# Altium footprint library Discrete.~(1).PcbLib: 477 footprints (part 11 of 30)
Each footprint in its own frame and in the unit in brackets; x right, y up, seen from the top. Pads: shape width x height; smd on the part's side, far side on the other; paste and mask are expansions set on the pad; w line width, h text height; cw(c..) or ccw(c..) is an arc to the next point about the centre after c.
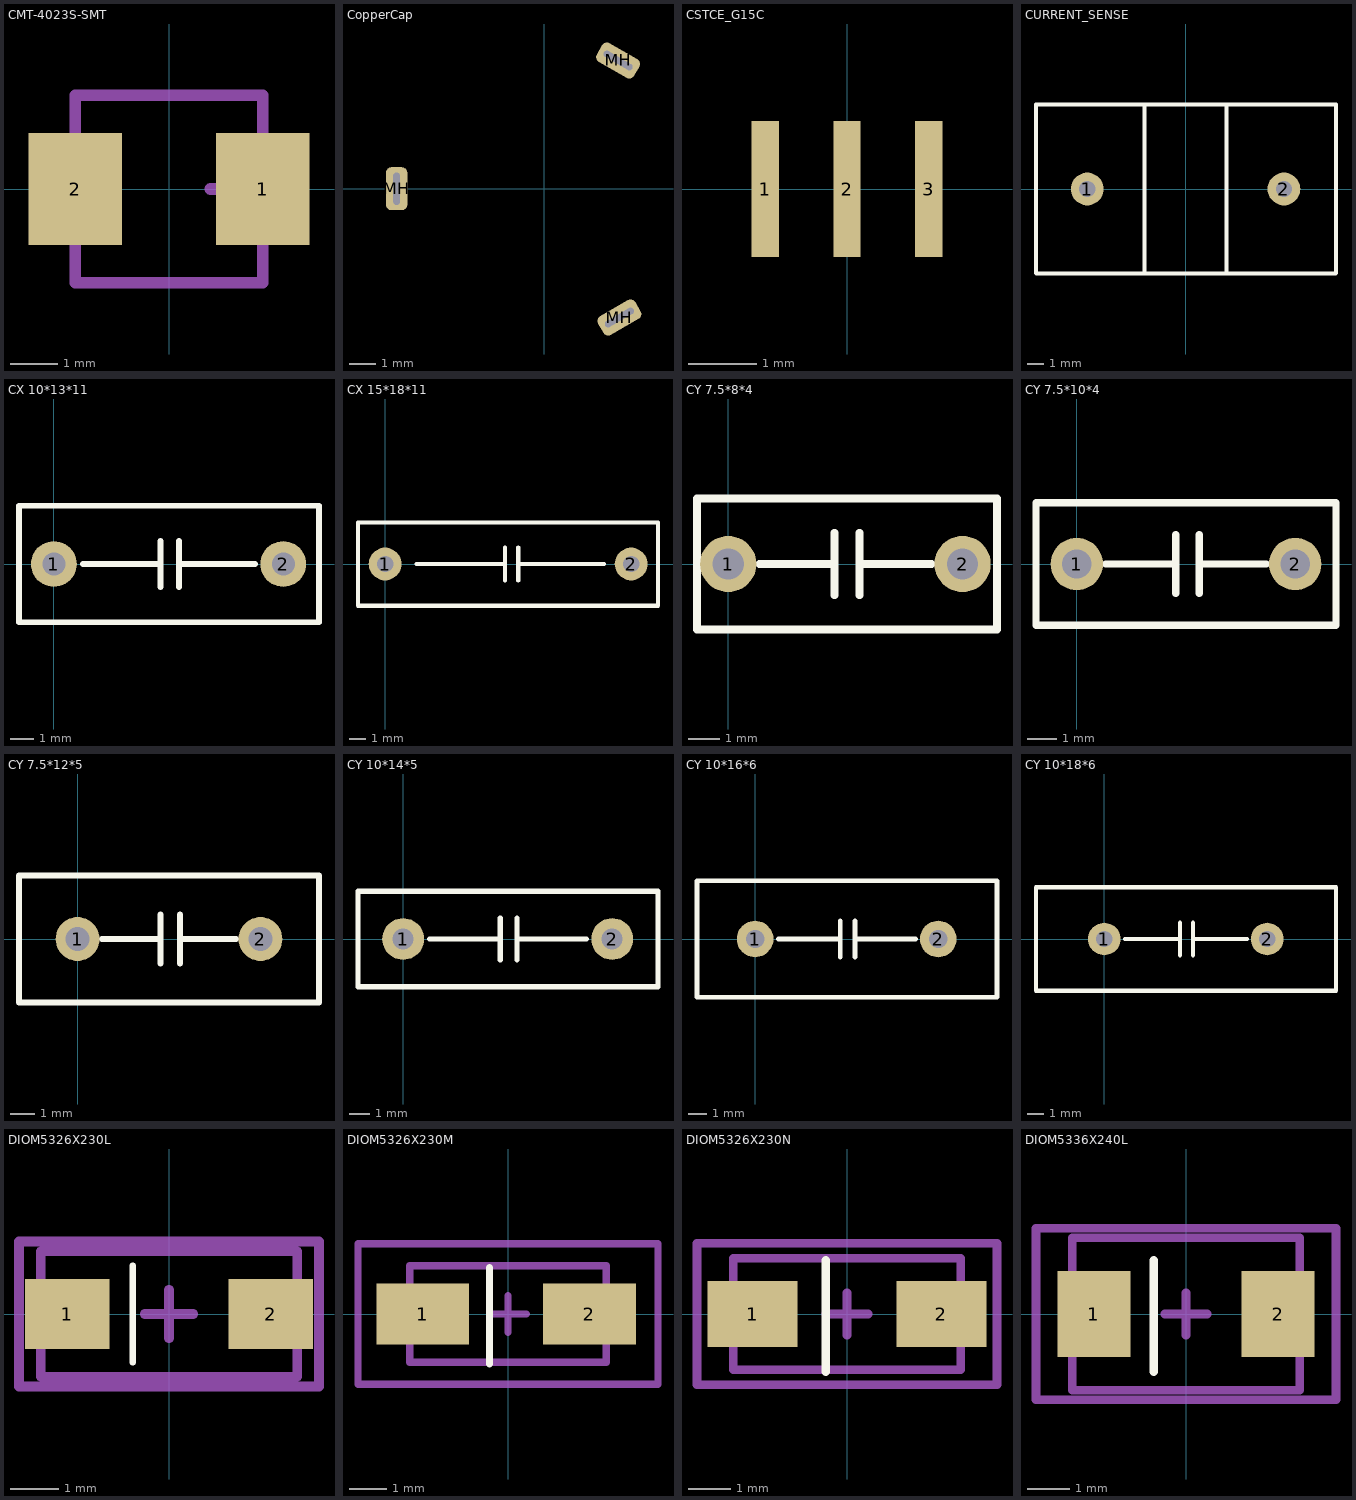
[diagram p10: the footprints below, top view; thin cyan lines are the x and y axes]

## CMT-4023S-SMT [mm]
pads (2):
  rect 2x2.4 smd: 1(2,0) 2(-2,0)
Mechanical 13:
  lines w0.254: 0.889,0 1.651,0 ; 1.27,-0.381 1.27,0.381 ; -2,-2 -2,2 2,2 2,-2 -2,-2
3D body "CUI_INC_CMT-4023S-SMT.step": height 2, standoff 0, extent -2,-2 2,2

## CopperCap [mm]
pads (3):
  rrect50% 0.8x1.6 hole 0.24 slot 1.2 at 90 deg: MH(-5.5,0)
  rrect50% 0.8x1.6 hole 0.24 slot 1.2 at 150 deg rot 60: MH(2.751,4.776)
  rrect50% 0.8x1.6 hole 0.24 slot 1.2 at 30 deg rot 120: MH(2.8,-4.8)
3D body "copper cap v5.step": height 2.1, standoff -0.9, extent -8.879,-8.879 8.869,8.863

## CSTCE_G15C [mm]
pads (3):
  rect 0.4x2 smd: 1(-1.2,0) 2(0,0) 3(1.2,0)
3D body "SW3dPS-CSTCE.STEP": height 0.7, standoff 0, extent -1.6,-0.65 1.6,0.65

## CURRENT_SENSE [mm]
pads (2):
  round 2 hole 1: 1(-6,0) 2(6,0)
Top Overlay:
  lines w0.254: -2.5,-5.125 -2.5,5.15 ; 2.5,-5.15 2.5,5.075 ; 9.15,-5.15 -9.1,-5.15 -9.125,-5.125 -9.125,5.15 9.175,5.15 9.175,-5.125

## CX 10*13*11 [mm] "脚距10mm高13mm厚11mm"
pads (2):
  round 2 hole 1: 1(0,0) 2(10,0)
Top Overlay:
  lines w0.254: 1.27,0 4.55,0 ; 4.65,-1 4.65,1 ; 5.45,-1 5.45,1 ; 5.45,0 8.763,0 ; -1.524,-2.54 -1.524,2.54 11.557,2.54 11.557,-2.54 -1.524,-2.54
3D body "CX 10X13X11.STEP": height 11.02, standoff -3.48, extent -1.5,-2.5 11.5,2.5

## CX 15*18*11 [mm] "脚距15mm高18mm厚11mm"
pads (2):
  round 2 hole 1: 1(0,0) 2(15,0)
Top Overlay:
  lines w0.254: 1.905,0 7.217,0 ; 7.317,-1 7.317,1 ; 8.117,-1 8.117,1 ; 8.117,0 13.335,0 ; -1.651,-2.54 -1.651,2.54 16.637,2.54 16.637,-2.54 -1.651,-2.54
3D body "CX 15X18X11.STEP": height 11.02, standoff -3.48, extent -1.5,-2.5 16.5,2.5

## CY 7.5*8*4 [mm] "脚距7.5mm，直径8mm，厚4mm"
pads (2):
  round 1.8 hole 1: 1(0,0) 2(7.5,0)
Top Overlay:
  lines w0.254: 1,0 3.3,0 ; 3.4,-1 3.4,1 ; 4.2,-1 4.2,1 ; 4.2,0 6.5,0 ; -1,-2.1 -1,2.1 8.6,2.1 8.6,-2.1 -1,-2.1
3D body "CY 7.5X8X4.STEP": height 8.2, standoff -3.3, extent -0.292,-2 7.792,2

## CY 7.5*10*4 [mm] "脚距7.5mm，直径10mm，厚4mm"
pads (2):
  round 1.8 hole 1: 1(0,0) 2(7.5,0)
Top Overlay:
  lines w0.254: 1,0 3.3,0 ; 3.4,-1 3.4,1 ; 4.2,-1 4.2,1 ; 4.2,0 6.5,0 ; -1.4,-2.1 -1.4,2.1 8.9,2.1 8.9,-2.1 -1.4,-2.1
3D body "CY 7.5X10X4.STEP": height 10.2, standoff -3.3, extent -1.13,-2 8.87,2

## CY 7.5*12*5 [mm] "脚距7.5mm，直径12mm，厚5mm"
pads (2):
  round 1.8 hole 1: 1(0,0) 2(7.5,0)
Top Overlay:
  lines w0.254: 1,0 3.3,0 ; 3.4,-1 3.4,1 ; 4.2,-1 4.2,1 ; 4.2,0 6.5,0 ; -2.4,-2.6 -2.4,2.6 9.9,2.6 9.9,-2.6 -2.4,-2.6
3D body "CY 7.5X12X5.STEP": height 12.2, standoff -3.3, extent -2.25,-2.5 9.75,2.5

## CY 10*14*5 [mm] "脚距10mm，直径14mm，厚5mm"
pads (2):
  round 2 hole 1: 1(0,0) 2(10,0)
Top Overlay:
  lines w0.254: 1.27,0 4.55,0 ; 4.65,-1 4.65,1 ; 5.45,-1 5.45,1 ; 5.45,0 8.763,0 ; -2.159,-2.286 -2.159,2.286 12.192,2.286 12.192,-2.286 -2.159,-2.286
3D body "CY 10X14X5.STEP": height 14.2, standoff -3.3, extent -2,-2 12,2

## CY 10*16*6 [mm] "脚距10mm，直径16mm，厚6mm"
pads (2):
  round 2 hole 1: 1(0,0) 2(10,0)
Top Overlay:
  lines w0.254: 1.27,0 4.55,0 ; 4.65,-1 4.65,1 ; 5.45,-1 5.45,1 ; 5.45,0 8.763,0 ; -3.175,-3.175 13.208,-3.175 13.208,3.175 -3.175,3.175 -3.175,-3.175
3D body "CY 10X16X6.STEP": height 16.2, standoff -3.3, extent -3,-3 13,3

## CY 10*18*6 [mm] "脚距10mm，直径18mm，厚6mm"
pads (2):
  round 2 hole 1: 1(0,0) 2(10,0)
Top Overlay:
  lines w0.254: 1.27,0 4.55,0 ; 4.65,-1 4.65,1 ; 5.45,-1 5.45,1 ; 5.45,0 8.763,0 ; -4.191,-3.175 -4.191,3.175 14.224,3.175 14.224,-3.175 -4.191,-3.175
3D body "CY 10X18X6.STEP": height 18.2, standoff -3.3, extent -4,-3 14,3

## DIOM5326X230L [mm] "Diode with Molded Body, DO-214AC,SMA"
height 2.3
pads (2):
  rect 1.75x1.45 smd: 1(-2.1,0) 2(2.1,0)
Top Overlay:
  lines w0.127: -0.75,-1 -0.75,1
Mechanical 13:
  lines w0.2: -2.65,-1.3 -2.65,1.3 2.65,1.3 2.65,-1.3 -2.65,-1.3
Mechanical 15:
  lines w0.2: -0.5,0 0.5,0 ; 0,-0.5 0,0.5 ; -3.1,-1.5 -3.1,1.5 3.1,1.5 3.1,-1.5 -3.1,-1.5
3D body "SMA.STEP": height 2.15, standoff 0.04, extent -2.552,-1.3 2.551,1.3

## DIOM5326X230M [mm] "Diode with Molded Body. DO-214AC, SMA"
height 2.3
pads (2):
  rect 2.5x1.65 smd: 1(-2.3,0) 2(2.2,0)
Top Overlay:
  lines w0.2: -0.5,-1.35 -0.5,1.25
Mechanical 13:
  lines w0.2: -2.65,-1.3 2.65,-1.3 2.65,1.3 -2.65,1.3 -2.65,-1.3
Mechanical 15:
  lines w0.2: -0.5,0 0.5,0 ; 0,-0.5 0,0.5 ; -4.05,-1.9 4.05,-1.9 4.05,1.9 -4.05,1.9 -4.05,-1.9
3D body "SMA.STEP": height 2.15, standoff 0.04, extent -2.552,-1.3 2.551,1.3

## DIOM5326X230N [mm] "Diode with Molded Body DO-214AC,SMA"
pads (2):
  rect 2.1x1.55 smd: 1(-2.2,0) 2(2.2,0)
Top Overlay:
  lines w0.2: -0.5,-1.35 -0.5,1.25
Mechanical 13:
  lines w0.2: -2.65,-1.3 -2.65,1.3 2.65,1.3 2.65,-1.3 -2.65,-1.3
Mechanical 15:
  lines w0.2: -0.5,0 0.5,0 ; 0,-0.5 0,0.5 ; -3.5,-1.65 -3.5,1.65 3.5,1.65 3.5,-1.65 -3.5,-1.65
3D body "SMA.STEP": height 2.15, standoff 0.04, extent -2.552,-1.3 2.551,1.3

## DIOM5336X240L [mm] "Diode with Molded Body DO-214AA, SMB"
height 2.4
pads (2):
  rect 1.7x2 smd: 1(-2.15,0) 2(2.15,0)
Top Overlay:
  lines w0.2: -0.75,-1.35 -0.75,1.25
Mechanical 13:
  lines w0.2: -2.65,-1.775 -2.65,1.775 2.65,1.775 2.65,-1.775 -2.65,-1.775
Mechanical 15:
  lines w0.2: -0.5,0 0.5,0 ; 0,-0.5 0,0.5 ; -3.5,-2 -3.5,2 3.5,2 3.5,-2 -3.5,-2
3D body "SMB.STEP": height 2.35, standoff 0.04, extent -2.629,-1.8 2.675,1.8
